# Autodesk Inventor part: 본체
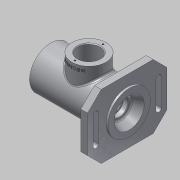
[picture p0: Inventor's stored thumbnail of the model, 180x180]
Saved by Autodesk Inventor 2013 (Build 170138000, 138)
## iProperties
Created: 2017-10
Part Number: 본체
Material: 알루미늄 6061
Document SubType Name: Modeling
Designer: dgall
Density: 1 g/cm^3
Author: dgall
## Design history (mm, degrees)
sketch "스케치1"
  geometry: L1 (0, 0)-(115, 0); L2 (0, 20)-(9, 20); L3 (9, 20)-(9, 24); L4 (9, 24)-(12, 24); L5 (12, 24)-(12, 20); L6 (12, 20)-(21, 20); L7 (21, 20)-(21, 17.5); L8 (21, 17.5)-(24.25, 17.5); L9 (24.25, 17.5)-(24.25, 18.5); L10 (24.25, 18.5)-(26, 18.5); L11 (26, 18.5)-(26, 16.5); L12 (26, 16.5)-(37, 16.5); L13 (37, 16.5)-(37, 26); L14 (75, 26)-(75, 17.5); L15 (75, 17.5)-(86, 17.5); L16 (86, 17.5)-(86, 16.5); L17 (86, 16.5)-(91, 16.5); L18 (91, 16.5)-(91, 10); L19 (91, 10)-(93.7, 10); L20 (93.7, 10)-(93.7, 12.5); L21 (93.7, 12.5)-(101, 12.5); L22 (101, 12.5)-(101, 16); L23 (101, 16)-(115, 22); L24 (0, 20)-(0, 31); L25 (0, 31)-(115, 31); L26 (115, 31)-(115, 22); L27 (37, 26)-(75, 26)
  constraints: 54 end point, 21 parallel, 3 perpendicular, 1 collinear, 1 horizontal, 1 vertical alignment
  dimensions: "d0" = 115 distance of L1.start L1.end; "d1" = 62 diameter of L25 L1; "d2" = 48 diameter of L4 L1; "d3" = 40 diameter of L6 L1; "d4" = 40 diameter of L2 L1; "d5" = 35 diameter of L8 L1; "d6" = 37 diameter of L10 L1; "d7" = 33 diameter of L12 L1; "d8" = 44 diameter of L23.end L1; "d9" = 32 diameter of L22.end L1; "d10" = 25 diameter of L21 L1; "d11" = 20 diameter of L19 L1; "d13" = 33 diameter of L17 L1; "d14" = 35 diameter of L15 L1; "d16" = 52 diameter of L27 L1; "d17" = 38 distance of L13.end L14.start; "d18" = 115 distance between parallel lines of L24 L26; "d20" = 3 distance of L3.end L4.end; "d21" = 12 distance between parallel lines of L24 L5; "d22" = 21 distance between parallel lines of L24 L7; "d23" = 26 distance between parallel lines of L24 L11; "d24" = 1.75 distance of L9.end L10.end; "d25" = 11 distance of L11.end L12.end; "d27" = 60 distance of L11.end L16.end; "d28" = 5 distance from line of L18 L15.end; "d29" = 14 horizontal distance of L22.end L23.end; "d30" = 2.7 distance of L18.end L19.end
revolve "회전1" sketch "스케치1" stored, may be unused: angle "d31" = 90 deg
node "작업 평면1"
sketch "스케치2"
  geometry: C1 r 25 at (56, 0); 1 further point
  constraints: 1 centre point, 1 horizontal alignment
  dimensions: "d33" = 56 distance of point (0, 0) C1.centre; "d34" = 50 diameter of C1
extrude "돌출1" join sketch "스케치2" stored distance "d35" = 10; taper "d36" = 0 deg
sketch "스케치3"
  geometry: C1 r 25 at (0, 0) reference; C2 r 16 at (0, 0); 1 further point
  constraints: 1 centre point, 1 coincident
  dimensions: "d37" = 32 diameter of C2
extrude "돌출2" cut sketch "스케치3" stored distance "d39" = 10; taper "d40" = 0 deg
node "작업 평면2"
sketch "스케치5"
  geometry: L1 (47, -58)-(-47, -58); L2 (-47, -58)-(-47, 58); L3 (-47, 58)-(47, 58); L4 (47, 58)-(47, -58); L5 (47, -58)-(-47, 58); L6 (-47, -58)-(47, 58); C1 r 31 at (0, 0) reference; C2 r 20.714 at (0, 0) reference; C3 r 31 at (0, 0) reference; C4 r 20.714 at (0, 0) reference; 1 further point
  constraints: 12 end point, 2 midpoint, 2 parallel, 1 horizontal, 1 perpendicular
  dimensions: "d42" = 94 distance of L1.start L1.end; "d44" = 116 distance of L3.end L1.start
extrude "돌출3" join sketch "스케치5" distance "d45" = 10; taper "d46" = 0 deg
chamfer "모따기1" distance "d47" = 20; stored, may be unused: second distance "d48" = 2, angle "d49" = 45 deg
sketch "스케치6"
  geometry: L1 (20, 50)-(-20, 50); L2 (20, 42)-(-20, 42); C1 r 31 at (0, 0) reference; A1 r 4 centre (20, 46) between (20, 42) and (20, 50); A2 r 4 centre (-20, 46) between (-20, 50) and (-20, 42)
  constraints: 4 end point, 4 point on circle, 4 tangent, 2 centre point, 1 equal radius
  dimensions: "d50" = 46 vertical distance of C1.centre A1.centre; "d51" = 46 vertical distance of A2.centre C1.centre; "d52" = 8 diameter of A1; "d53" = 20 horizontal distance of A2.centre C1.centre; "d54" = 20 horizontal distance of C1.centre A1.centre
extrude "돌출4" cut sketch "스케치6" stored distance "d55" = 10; taper "d56" = 0 deg
node "작업 평면3"
sketch "스케치7" dims "d57" = 41
  geometry: C1 r 16 at (0, 0) reference; C2 r 25 at (0, 0) reference; 3 further points
  constraints: 2 vertical alignment, 1 coincident, 2 other
hole "구멍1" sketch "스케치7" at (0, 20.5) diameter "d59" = 2.459; stored, may be unused: countersink angle "d63" = 90 deg, drill point angle "d65" = 118 deg; dims "d60" = 6, "d61" = 4, "d62" = 2, "d64" = 8
fillet "모깎기1" dims "d69" = 3
fillet "모깎기2" dims "d70" = 3
chamfer "모따기2" distance "d71" = 1; stored, may be unused: second distance "d72" = 2, angle "d73" = 45 deg
fillet "모깎기3" dims "d74" = 3
fillet "모깎기4" dims "d75" = 3
fillet "모깎기5" dims "d76" = 0.3
fillet "모깎기6" dims "d80" = 3
chamfer "모따기4" distance "d81" = 0.41; stored, may be unused: second distance "d82" = 2, angle "d83" = 60 deg
node "작업 평면4"
sketch "스케치14"
  geometry: L1 (39.408, 43.402)-(72.592, 43.402); L2 (72.592, 43.402)-(72.592, 38.598); L3 (72.592, 38.598)-(39.408, 38.598); L4 (39.408, 38.598)-(39.408, 43.402); L5 (0, 31)-(99, 31) reference; L6 (31, 47)-(81, 47) reference; L7 (39.408, 41)-(72.592, 41); L8 (56, 43.402)-(56, 38.598); 1 further point
  constraints: 4 end point, 4 midpoint, 2 other
  dimensions: "d86" = 56 distance from line of L5.start L8; "d87" = 10 distance between parallel lines of L5 L7
feature "엠보싱1" sketch "스케치14" dims "d0" = 115, "d1" = 62, "d2" = 48, "d3" = 40, "d4" = 40, "d5" = 35, "d6" = 37, "d7" = 33, "d8" = 44, "d9" = 32, "d10" = 25, "d11" = 20, "d13" = 33, "d14" = 35, "d16" = 52, "d17" = 38, "d18" = 115, "d20" = 3, "d21" = 12, "d22" = 21, "d23" = 26, "d24" = 1.75, "d25" = 11, "d27" = 60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
feature "스레드2" dims "d92" = 10, "d93" = 0
chamfer "모따기5" distance "d94" = 1; stored, may be unused: second distance "d95" = 2, angle "d96" = 45 deg
node "솔리드1"
mirror "대칭1"
pattern_circular "원형 패턴1" dims angle "d67" = 360 deg
node "절단 모서리 투영1"
node "절단 모서리 투영2"
other parameters: "d32" = 47, "d41" = -3, "d84" = -25.3
